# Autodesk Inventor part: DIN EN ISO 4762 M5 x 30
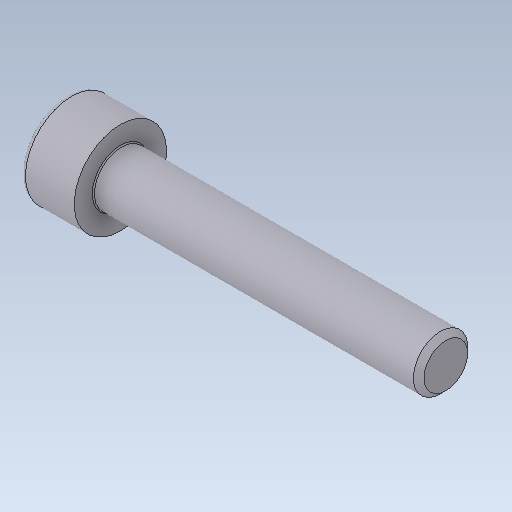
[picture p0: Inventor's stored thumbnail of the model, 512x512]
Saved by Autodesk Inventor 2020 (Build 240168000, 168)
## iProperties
Created: 2017-11
Part Number: DIN EN ISO 4762 M5 x 30
Material: Ogólny
Document SubType Name: Modeling
Designer: Tomasz
Density: 1 g/cm^3
Appearance: Domyślna
Author: Tomasz
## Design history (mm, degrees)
feature "Solid1"
node "Bryła1"
